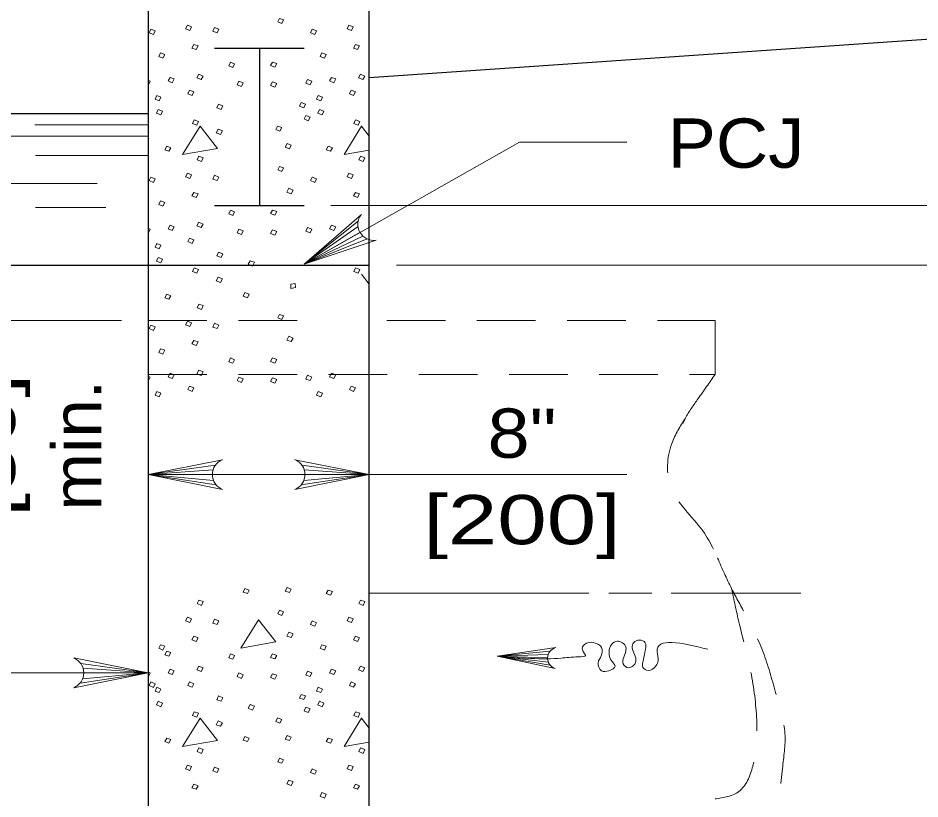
# Model space of a CAD drawing. Extents: x 1083.1 to 1123, y 697.4 to 741.4.
# Drawn here: x 1094.048 to 1096.906, y 701.287 to 703.761 of the extents above; entities that cross this region are included whole.
import ezdxf
from ezdxf.enums import TextEntityAlignment as Align

# ---------------------------------------------------------------- set-up
doc = ezdxf.new("R2010")
doc.units = 0
doc.header["$LTSCALE"] = 0.062
doc.linetypes.add('MEDIUM_DASHED', pattern=[4.5, 3, -1.5])
doc.layers.add('1', color=7, linetype='Continuous', lineweight=13)

msp = doc.modelspace()

# ---------------------------------------------------------------- linework, layer by layer
at = {"layer": '1', "lineweight": 25}
for p, q in [((1095.16083, 699.49442), (1095.16083, 704.3885)), ((1094.45983, 704.08583), (1094.45983, 702.96883)), ((1095.16083, 703.57292), (1099.30092, 703.85675)), ((1094.67075, 703.66558), (1094.95483, 703.66558)), ((1094.81283, 703.66558), (1094.81283, 703.167)), ((1092.13858, 703.45842), (1094.45983, 703.45842)), ((1094.67075, 703.167), (1094.95483, 703.167)), ((1094.45983, 702.97792), (1094.45983, 700.85858))]:
    msp.add_line(p, q, dxfattribs=at)
at = {"layer": '1'}
for p, q in [((1094.10067, 703.42283), (1094.45983, 703.42283)), ((1095.16083, 703.38692), (1095.1365, 703.41817)), ((1093.84958, 703.38742), (1094.45983, 703.38742)), ((1094.10292, 703.32575), (1094.45983, 703.32575)), ((1093.95833, 703.23683), (1094.29858, 703.23683)), ((1094.10292, 703.16125), (1094.32633, 703.16125)), ((1095.03908, 703.167), (1100.20558, 703.167)), ((1095.12558, 703.11725), (1094.95433, 702.98183)), ((1095.12533, 703.10117), (1094.95433, 702.98183)), ((1095.1315, 703.08267), (1094.95433, 702.98183)), ((1095.14092, 703.07067), (1094.95433, 702.98183)), ((1095.1545, 703.06142), (1094.95433, 702.98183)), ((1095.07658, 702.97792), (1094.07242, 702.97792)), ((1095.247, 702.97792), (1100.93725, 702.97792)), ((1095.33125, 702.97792), (1096.6295, 702.97792)), ((1095.16083, 702.91817), (1095.1365, 702.9495)), ((1094.37558, 702.80275), (1093.74558, 702.80275)), ((1094.67317, 702.34492), (1094.45983, 702.31508)), ((1094.9475, 702.34492), (1095.16083, 702.31508)), ((1094.66592, 702.33017), (1094.45983, 702.31508)), ((1094.45983, 702.31508), (1095.97717, 702.31508)), ((1094.66367, 702.31508), (1094.45983, 702.31508)), ((1094.6675, 702.29592), (1094.45983, 702.31508)), ((1094.67567, 702.28208), (1094.45983, 702.31508)), ((1094.945, 702.28208), (1095.16083, 702.31508)), ((1094.95317, 702.29592), (1095.16083, 702.31508)), ((1094.95475, 702.33017), (1095.16083, 702.31508)), ((1094.95692, 702.31508), (1095.16083, 702.31508)), ((1095.85708, 701.93967), (1095.16083, 701.93967)), ((1096.05675, 701.93967), (1095.92, 701.93967)), ((1096.529, 701.93967), (1096.11758, 701.93967)), ((1095.73417, 701.75567), (1095.56583, 701.73925)), ((1095.72808, 701.74533), (1095.56583, 701.73925)), ((1095.726, 701.73475), (1095.56583, 701.73925)), ((1095.7285, 701.72108), (1095.56583, 701.73925)), ((1095.73458, 701.71108), (1095.56583, 701.73925)), ((1094.24658, 701.71675), (1094.45983, 701.68692)), ((1094.24408, 701.65392), (1094.45983, 701.68692)), ((1094.25225, 701.66775), (1094.45983, 701.68692)), ((1094.25383, 701.702), (1094.45983, 701.68692)), ((1094.256, 701.68692), (1094.45983, 701.68692)), ((1095.16083, 701.51208), (1095.1365, 701.54333))]:
    msp.add_line(p, q, dxfattribs=at)
at = {"layer": '1', "linetype": 'MEDIUM_DASHED'}
for p, q in [((1094.45983, 702.80275), (1094.95575, 702.80275)), ((1095.21608, 702.80275), (1096.25675, 702.80275)), ((1096.25675, 702.80275), (1096.25675, 702.63158)), ((1094.45983, 702.63158), (1096.25675, 702.63158))]:
    msp.add_line(p, q, dxfattribs=at)
at = {"layer": '1'}
for points in [[(1094.87608, 703.76), (1094.8895, 703.75517), (1094.88417, 703.74383), (1094.87067, 703.74867)], [(1094.46833, 703.72608), (1094.48183, 703.72042), (1094.47642, 703.70908), (1094.463, 703.71475)], [(1094.58425, 703.73817), (1094.59767, 703.73333), (1094.59225, 703.72125), (1094.57883, 703.72683)], [(1094.67042, 703.73175), (1094.68392, 703.72608), (1094.6785, 703.71475), (1094.665, 703.71958)], [(1094.98025, 703.72608), (1094.99367, 703.72042), (1094.98833, 703.70908), (1094.97483, 703.71475)], [(1095.09608, 703.73817), (1095.10958, 703.73333), (1095.10417, 703.72125), (1095.09067, 703.72683)], [(1094.60492, 703.67758), (1094.61833, 703.67275), (1094.61208, 703.66142), (1094.59858, 703.66625)], [(1095.11675, 703.67758), (1095.13017, 703.67275), (1095.12392, 703.66142), (1095.11042, 703.66625)], [(1094.49892, 703.65092), (1094.51242, 703.64608), (1094.507, 703.63392), (1094.4935, 703.63958)], [(1095.01075, 703.65092), (1095.02425, 703.64608), (1095.01883, 703.63392), (1095.00542, 703.63958)], [(1094.72067, 703.62183), (1094.73417, 703.61617), (1094.72883, 703.60483), (1094.71533, 703.60967)], [(1094.8545, 703.62183), (1094.868, 703.617), (1094.86167, 703.60567), (1094.84825, 703.6105)], [(1094.52942, 703.57333), (1094.54292, 703.5685), (1094.53658, 703.55633), (1094.52317, 703.562)], [(1094.621, 703.583), (1094.6345, 703.57742), (1094.62825, 703.56608), (1094.61475, 703.57175)], [(1095.04133, 703.57333), (1095.05475, 703.5685), (1095.0485, 703.55633), (1095.035, 703.562)], [(1095.13292, 703.583), (1095.14633, 703.57742), (1095.14008, 703.56608), (1095.12658, 703.57175)], [(1094.74767, 703.56125), (1094.76108, 703.55558), (1094.75575, 703.54425), (1094.74225, 703.54992)], [(1094.8545, 703.55883), (1094.868, 703.55392), (1094.86167, 703.54183), (1094.84825, 703.5475)], [(1094.965, 703.56683), (1094.97842, 703.56125), (1094.97308, 703.54992), (1094.95958, 703.55475)], [(1094.48725, 703.516), (1094.50067, 703.51033), (1094.49533, 703.499), (1094.48183, 703.50383)], [(1094.59142, 703.53292), (1094.60492, 703.52725), (1094.5995, 703.516), (1094.586, 703.52158)], [(1094.99908, 703.516), (1095.01258, 703.51033), (1095.00717, 703.499), (1094.99367, 703.50383)], [(1095.10325, 703.53292), (1095.11675, 703.52725), (1095.11133, 703.516), (1095.09783, 703.52158)], [(1094.683, 703.4885), (1094.6965, 703.48283), (1094.69108, 703.4715), (1094.67758, 703.47633)], [(1094.94517, 703.49333), (1094.95867, 703.4885), (1094.95333, 703.47717), (1094.93983, 703.482)], [(1094.49175, 703.4715), (1094.50517, 703.46583), (1094.49983, 703.45458), (1094.48633, 703.46017)], [(1095.00358, 703.4715), (1095.01708, 703.46583), (1095.01167, 703.45458), (1094.99817, 703.46017)], [(1094.60575, 703.43842), (1094.61925, 703.4335), (1094.61383, 703.42142), (1094.60042, 703.42708)], [(1094.95958, 703.45292), (1094.97308, 703.44725), (1094.96767, 703.43592), (1094.95417, 703.44158)], [(1095.11767, 703.43842), (1095.13108, 703.4335), (1095.12575, 703.42142), (1095.11225, 703.42708)], [(1094.62467, 703.41817), (1094.56892, 703.3285), (1094.67942, 703.34783)], [(1094.68208, 703.40925), (1094.69558, 703.40367), (1094.68925, 703.39233), (1094.67583, 703.39717)], [(1094.86975, 703.419), (1094.88325, 703.41417), (1094.87783, 703.40283), (1094.86442, 703.40767)], [(1094.51867, 703.35517), (1094.53217, 703.35033), (1094.52583, 703.339), (1094.51242, 703.34383)], [(1094.90033, 703.36325), (1094.91375, 703.35842), (1094.9075, 703.34708), (1094.894, 703.35192)], [(1095.0305, 703.35517), (1095.044, 703.35033), (1095.03767, 703.339), (1095.02425, 703.34383)], [(1094.621, 703.32367), (1094.6345, 703.31875), (1094.62908, 703.30667), (1094.61567, 703.31233)], [(1095.13292, 703.32367), (1095.14633, 703.31875), (1095.141, 703.30667), (1095.1275, 703.31233)], [(1094.87608, 703.29133), (1094.8895, 703.28642), (1094.88417, 703.27517), (1094.87067, 703.28)], [(1094.46833, 703.25733), (1094.48183, 703.25167), (1094.47642, 703.24042), (1094.463, 703.24608)], [(1094.58425, 703.2695), (1094.59767, 703.26467), (1094.59225, 703.2525), (1094.57883, 703.25817)], [(1094.67042, 703.263), (1094.68392, 703.25733), (1094.6785, 703.24608), (1094.665, 703.25092)], [(1094.98025, 703.25733), (1094.99367, 703.25167), (1094.98833, 703.24042), (1094.97483, 703.24608)], [(1095.09608, 703.2695), (1095.10958, 703.26467), (1095.10417, 703.2525), (1095.09067, 703.25817)], [(1094.60492, 703.20883), (1094.61833, 703.204), (1094.61208, 703.19275), (1094.59858, 703.19758)], [(1094.90567, 703.22183), (1094.91917, 703.21617), (1094.91292, 703.20483), (1094.89942, 703.20967)], [(1095.11675, 703.20883), (1095.13017, 703.204), (1095.12392, 703.19275), (1095.11042, 703.19758)], [(1094.49892, 703.18225), (1094.51242, 703.17733), (1094.507, 703.16525), (1094.4935, 703.17092)], [(1094.72067, 703.15308), (1094.73417, 703.1475), (1094.72883, 703.13617), (1094.71533, 703.141)], [(1094.8545, 703.15308), (1094.868, 703.14825), (1094.86167, 703.13692), (1094.84825, 703.14183)], [(1094.621, 703.11433), (1094.6345, 703.10867), (1094.62825, 703.09733), (1094.61475, 703.103)], [(1094.52942, 703.10467), (1094.54292, 703.09975), (1094.53658, 703.08767), (1094.52317, 703.09333)], [(1094.74767, 703.0925), (1094.76108, 703.08683), (1094.75575, 703.0755), (1094.74225, 703.08117)], [(1094.8545, 703.09008), (1094.868, 703.08525), (1094.86167, 703.07308), (1094.84825, 703.07875)], [(1094.965, 703.09817), (1094.97842, 703.0925), (1094.97308, 703.08117), (1094.95958, 703.086)], [(1095.04133, 703.10467), (1095.05475, 703.09975), (1095.0485, 703.08767), (1095.035, 703.09333)], [(1094.59142, 703.06425), (1094.60492, 703.05858), (1094.5995, 703.04725), (1094.586, 703.05292)], [(1094.48725, 703.04725), (1094.50067, 703.04158), (1094.49533, 703.03025), (1094.48183, 703.03517)], [(1094.49175, 703.00283), (1094.50517, 702.99717), (1094.49983, 702.98583), (1094.48633, 702.9915)], [(1094.683, 703.01975), (1094.6965, 703.01408), (1094.69108, 703.00283), (1094.67758, 703.00767)], [(1094.60575, 702.96967), (1094.61925, 702.96483), (1094.61383, 702.95267), (1094.60042, 702.95833)], [(1094.78358, 702.99233), (1094.797, 702.98742), (1094.79075, 702.97533), (1094.77725, 702.981)], [(1095.11767, 702.96967), (1095.13108, 702.96483), (1095.12575, 702.95267), (1095.11225, 702.95833)], [(1094.68208, 702.94058), (1094.69558, 702.93492), (1094.68925, 702.92358), (1094.67583, 702.9285)], [(1094.92692, 702.90742), (1094.91258, 702.90492), (1094.91175, 702.91783), (1094.92617, 702.92033)], [(1094.51867, 702.88642), (1094.53217, 702.88158), (1094.52583, 702.87025), (1094.51242, 702.87517)], [(1094.7665, 702.89133), (1094.78, 702.88642), (1094.77458, 702.87517), (1094.76108, 702.88)], [(1094.621, 702.85492), (1094.6345, 702.85008), (1094.62908, 702.83792), (1094.61567, 702.84358)], [(1094.58425, 702.80075), (1094.59767, 702.79592), (1094.59225, 702.78383), (1094.57883, 702.7895)], [(1094.87608, 702.82258), (1094.8895, 702.81775), (1094.88417, 702.80642), (1094.87067, 702.81125)], [(1094.46833, 702.78867), (1094.48183, 702.783), (1094.47642, 702.77167), (1094.463, 702.77733)], [(1094.67042, 702.79433), (1094.68392, 702.78867), (1094.6785, 702.77733), (1094.665, 702.78217)], [(1094.60492, 702.74017), (1094.61833, 702.73533), (1094.61208, 702.724), (1094.59858, 702.72883)], [(1094.90567, 702.75308), (1094.91917, 702.74742), (1094.91292, 702.73617), (1094.89942, 702.741)], [(1094.49892, 702.7135), (1094.51242, 702.70867), (1094.507, 702.6965), (1094.4935, 702.70217)], [(1094.72067, 702.68442), (1094.73417, 702.67875), (1094.72883, 702.66742), (1094.71533, 702.67225)], [(1094.8545, 702.68442), (1094.868, 702.67958), (1094.86167, 702.66825), (1094.84825, 702.67308)], [(1094.52942, 702.63592), (1094.54292, 702.63108), (1094.53658, 702.61892), (1094.52317, 702.62458)], [(1094.621, 702.64558), (1094.6345, 702.64), (1094.62825, 702.62867), (1094.61475, 702.63433)], [(1094.965, 702.62942), (1094.97842, 702.62383), (1094.97308, 702.6125), (1094.95958, 702.61733)], [(1095.04133, 702.63592), (1095.05475, 702.63108), (1095.0485, 702.61892), (1095.035, 702.62458)], [(1094.74767, 702.62383), (1094.76108, 702.61817), (1094.75575, 702.60683), (1094.74225, 702.6125)], [(1094.8545, 702.62133), (1094.868, 702.6165), (1094.86167, 702.60442), (1094.84825, 702.61008)], [(1094.48725, 702.57858), (1094.50067, 702.57292), (1094.49533, 702.56158), (1094.48183, 702.56642)], [(1094.59142, 702.5955), (1094.60492, 702.58983), (1094.5995, 702.57858), (1094.586, 702.58417)], [(1094.99908, 702.57858), (1095.01258, 702.57292), (1095.00717, 702.56158), (1094.99367, 702.56642)], [(1095.10325, 702.5955), (1095.11675, 702.58983), (1095.11133, 702.57858), (1095.09783, 702.58417)], [(1094.7665, 701.95383), (1094.78, 701.949), (1094.77458, 701.93775), (1094.76108, 701.94258)], [(1094.90033, 701.95708), (1094.91375, 701.95225), (1094.9075, 701.94092), (1094.894, 701.94575)], [(1095.0305, 701.949), (1095.044, 701.94417), (1095.03767, 701.93283), (1095.02425, 701.93775)], [(1094.621, 701.9175), (1094.6345, 701.91267), (1094.62908, 701.9005), (1094.61567, 701.90617)], [(1095.13292, 701.9175), (1095.14633, 701.91267), (1095.141, 701.9005), (1095.1275, 701.90617)], [(1094.87608, 701.88517), (1094.8895, 701.88033), (1094.88417, 701.869), (1094.87067, 701.87383)], [(1094.58425, 701.86333), (1094.59767, 701.8585), (1094.59225, 701.84642), (1094.57883, 701.85208)], [(1094.67042, 701.85692), (1094.68392, 701.85125), (1094.6785, 701.83992), (1094.665, 701.84475)], [(1094.80958, 701.85525), (1094.75392, 701.76558), (1094.86442, 701.785)], [(1095.09608, 701.86333), (1095.10958, 701.8585), (1095.10417, 701.84642), (1095.09067, 701.85208)], [(1094.98025, 701.85125), (1094.99367, 701.84558), (1094.98833, 701.83425), (1094.97483, 701.83992)], [(1094.60492, 701.80275), (1094.61833, 701.79792), (1094.61208, 701.78658), (1094.59858, 701.79142)], [(1094.90567, 701.81567), (1094.91917, 701.81), (1094.91292, 701.79875), (1094.89942, 701.80358)], [(1095.11675, 701.80275), (1095.13017, 701.79792), (1095.12392, 701.78658), (1095.11042, 701.79142)], [(1094.49892, 701.77608), (1094.51242, 701.77125), (1094.507, 701.75908), (1094.4935, 701.76475)], [(1095.01075, 701.77608), (1095.02425, 701.77125), (1095.01883, 701.75908), (1095.00542, 701.76475)], [(1094.51867, 701.75575), (1094.53217, 701.75092), (1094.52583, 701.73958), (1094.51242, 701.74442)], [(1094.72067, 701.747), (1094.73417, 701.74133), (1094.72883, 701.73), (1094.71533, 701.73483)], [(1094.8545, 701.747), (1094.868, 701.74217), (1094.86167, 701.73083), (1094.84825, 701.73567)], [(1094.52942, 701.6985), (1094.54292, 701.69367), (1094.53658, 701.6815), (1094.52317, 701.68717)], [(1094.621, 701.70817), (1094.6345, 701.7025), (1094.62825, 701.69125), (1094.61475, 701.69692)], [(1094.74767, 701.68642), (1094.76108, 701.68075), (1094.75575, 701.66942), (1094.74225, 701.67508)], [(1094.8545, 701.684), (1094.868, 701.67908), (1094.86167, 701.667), (1094.84825, 701.67267)], [(1094.965, 701.692), (1094.97842, 701.68642), (1094.97308, 701.67508), (1094.95958, 701.67992)], [(1095.04133, 701.6985), (1095.05475, 701.69367), (1095.0485, 701.6815), (1095.035, 701.68717)], [(1095.13292, 701.70817), (1095.14633, 701.7025), (1095.14008, 701.69125), (1095.12658, 701.69692)], [(1094.46833, 701.65792), (1094.48183, 701.65233), (1094.47642, 701.641), (1094.463, 701.64667)], [(1094.59142, 701.65808), (1094.60492, 701.65242), (1094.5995, 701.64117), (1094.586, 701.64675)], [(1095.10325, 701.65808), (1095.11675, 701.65242), (1095.11133, 701.64117), (1095.09783, 701.64675)], [(1094.48725, 701.64117), (1094.50067, 701.6355), (1094.49533, 701.62417), (1094.48183, 701.629)], [(1094.99908, 701.64117), (1095.01258, 701.6355), (1095.00717, 701.62417), (1094.99367, 701.629)], [(1094.49175, 701.59667), (1094.50517, 701.591), (1094.49983, 701.57975), (1094.48633, 701.58533)], [(1094.683, 701.61367), (1094.6965, 701.608), (1094.69108, 701.59667), (1094.67758, 701.6015)], [(1094.94517, 701.6185), (1094.95867, 701.61367), (1094.95333, 701.60233), (1094.93983, 701.60717)], [(1095.00358, 701.59667), (1095.01708, 701.591), (1095.01167, 701.57975), (1094.99817, 701.58533)], [(1094.78358, 701.58617), (1094.797, 701.58133), (1094.79075, 701.56917), (1094.77725, 701.57483)], [(1094.95958, 701.57808), (1094.97308, 701.57242), (1094.96767, 701.56117), (1094.95417, 701.56675)], [(1094.62467, 701.54333), (1094.56892, 701.45367), (1094.67942, 701.473)], [(1094.60575, 701.56358), (1094.61925, 701.55867), (1094.61383, 701.54658), (1094.60042, 701.55225)], [(1094.86975, 701.54417), (1094.88325, 701.53933), (1094.87783, 701.528), (1094.86442, 701.53283)], [(1095.11767, 701.56358), (1095.13108, 701.55867), (1095.12575, 701.54658), (1095.11225, 701.55225)], [(1094.68208, 701.53442), (1094.69558, 701.52883), (1094.68925, 701.5175), (1094.67583, 701.52233)], [(1094.7665, 701.48517), (1094.78, 701.48033), (1094.77458, 701.469), (1094.76108, 701.47383)], [(1094.90033, 701.48842), (1094.91375, 701.48358), (1094.9075, 701.47225), (1094.894, 701.47708)], [(1094.51867, 701.48033), (1094.53217, 701.4755), (1094.52583, 701.46417), (1094.51242, 701.469)], [(1095.0305, 701.48033), (1095.044, 701.4755), (1095.03767, 701.46417), (1095.02425, 701.469)], [(1094.621, 701.44883), (1094.6345, 701.44392), (1094.62908, 701.43183), (1094.61567, 701.4375)], [(1095.13292, 701.44883), (1095.14633, 701.44392), (1095.141, 701.43183), (1095.1275, 701.4375)], [(1094.87608, 701.4165), (1094.8895, 701.41167), (1094.88417, 701.40033), (1094.87067, 701.40517)], [(1094.58425, 701.39467), (1094.59767, 701.38983), (1094.59225, 701.37767), (1094.57883, 701.38333)], [(1094.67042, 701.38817), (1094.68392, 701.3825), (1094.6785, 701.37125), (1094.665, 701.37608)], [(1094.98025, 701.3825), (1094.99367, 701.37683), (1094.98833, 701.36558), (1094.97483, 701.37125)], [(1095.09608, 701.39467), (1095.10958, 701.38983), (1095.10417, 701.37767), (1095.09067, 701.38333)], [(1094.90567, 701.347), (1094.91917, 701.34133), (1094.91292, 701.33), (1094.89942, 701.33483)], [(1094.60492, 701.33408), (1094.61833, 701.32917), (1094.61208, 701.31792), (1094.59858, 701.32275)], [(1095.11675, 701.33408), (1095.13017, 701.32917), (1095.12392, 701.31792), (1095.11042, 701.32275)], [(1095.01075, 701.30742), (1095.02425, 701.3025), (1095.01883, 701.29042), (1095.00542, 701.29608)]]:
    msp.add_lwpolyline(points, close=True, dxfattribs=at)
for points in [[(1094.45983, 703.564), (1094.46658, 703.56125), (1094.46117, 703.54992), (1094.45983, 703.55042)], [(1094.45983, 703.44783), (1094.46117, 703.44725), (1094.45983, 703.44442)], [(1095.1365, 703.41817), (1095.08083, 703.3285), (1095.16083, 703.3425)], [(1094.95433, 702.98183), (1095.63692, 703.36842), (1095.97717, 703.36842)], [(1095.13583, 703.13933), (1094.95433, 702.98183), (1095.18242, 703.05742)], [(1094.45983, 703.09533), (1094.46658, 703.0925), (1094.46117, 703.08117), (1094.45983, 703.08167)], [(1094.45983, 702.97908), (1094.46117, 702.97858), (1094.45983, 702.97575)], [(1094.45983, 702.62667), (1094.46658, 702.62383), (1094.46117, 702.6125), (1094.45983, 702.613)], [(1094.45983, 702.51042), (1094.46117, 702.50983), (1094.45983, 702.507)], [(1094.69542, 702.26792), (1094.45983, 702.31508), (1094.69542, 702.36217)], [(1094.92525, 702.26792), (1095.16083, 702.31508), (1094.92525, 702.36217)], [(1094.45983, 702.218), (1094.46117, 702.21742), (1094.45983, 702.21458)], [(1095.74983, 701.70067), (1095.56583, 701.73925), (1095.75208, 701.76733)], [(1094.22425, 701.63975), (1094.45983, 701.68692), (1094.22425, 701.734)], [(1092.13858, 701.68692), (1093.89508, 701.68692), (1094.45983, 701.68692)], [(1094.45983, 701.68925), (1094.46658, 701.68642), (1094.46117, 701.67508), (1094.45983, 701.67558)], [(1094.45983, 701.573), (1094.46117, 701.57242), (1094.45983, 701.56958)], [(1095.1365, 701.54333), (1095.08083, 701.45367), (1095.16083, 701.46767)]]:
    msp.add_lwpolyline(points, dxfattribs=at)
at = {"layer": '1', "lineweight": 25}
msp.add_lwpolyline([(1091.42492, 702.97792), (1092.13858, 702.97792), (1095.16083, 702.97792)], dxfattribs=at)
at = {"layer": '1'}
for centre, start, end in [((1095.17566, 703.10773), 141.73751, 277.56363), ((1094.71446, 702.31511), 112.08782, 247.91395), ((1094.90621, 702.31511), 292.08605, 67.91218), ((1094.20524, 701.68694), 292.08605, 67.91218)]:
    msp.add_arc(centre, 0.05085, start, end, dxfattribs=at)
msp.add_ellipse((1095.76597, 701.73359), major_axis=(-0.03997, 0), ratio=0.899905, start_param=5.0665441, end_param=7.4371572, dxfattribs=at)
at = {"layer": '1', "linetype": 'MEDIUM_DASHED'}
for points in [[(1096.25675, 702.63158), (1096.20333, 702.5555), (1096.16242, 702.49292), (1096.15175, 702.47108)], [(1096.16292, 702.49375), (1096.11958, 702.41342), (1096.11642, 702.27633), (1096.21808, 702.13625), (1096.28117, 702.01533)], [(1096.26467, 702.0505), (1096.3095, 701.95358), (1096.35508, 701.86883), (1096.41217, 701.7445), (1096.45117, 701.617), (1096.47833, 701.49367), (1096.47042, 701.384), (1096.44308, 701.23358), (1096.36575, 701.124), (1096.25675, 701.07533)], [(1096.25675, 701.28742), (1096.33233, 701.31108), (1096.3765, 701.39142), (1096.38892, 701.53767), (1096.37033, 701.69017), (1096.33267, 701.847), (1096.3095, 701.95358)]]:
    msp.add_spline(points, degree=3, dxfattribs=at)
at = {"layer": '1'}
msp.add_spline([(1096.23367, 701.76192), (1096.0735, 701.75383), (1096.07658, 701.72458), (1096.07017, 701.71), (1096.0445, 701.69442), (1096.0285, 701.70383), (1096.02967, 701.72783), (1096.03617, 701.76125), (1096.03525, 701.78217), (1096.01708, 701.79058), (1095.99892, 701.78225), (1095.9945, 701.76658), (1096.00192, 701.74458), (1096.00608, 701.72475), (1095.99425, 701.707), (1095.97717, 701.70392), (1095.96442, 701.72067), (1095.96992, 701.74258), (1095.97325, 701.77183), (1095.95942, 701.78433), (1095.94233, 701.7865), (1095.92517, 701.77192), (1095.92083, 701.75), (1095.93142, 701.72167), (1095.93983, 701.70808), (1095.9205, 701.69358), (1095.89708, 701.69358), (1095.8865, 701.71875), (1095.89617, 701.74058), (1095.89733, 701.76675), (1095.874, 701.78242), (1095.843, 701.77717), (1095.8365, 701.7595), (1095.846, 701.74175), (1095.82467, 701.73758), (1095.76908, 701.7335), (1095.56583, 701.73925)], degree=3, dxfattribs=at)

# ---------------------------------------------------------------- texts
at = {"layer": '1', "width": 1.1}
msp.add_text('PCJ', height=0.156, dxfattribs=at).set_placement((1096.10642, 703.287))
at = {"layer": '1'}
for s, width, p in [('[50]', 1.3, (1094.03808, 702.40771)), ('min.', 1.05, (1094.31208, 702.40775))]:
    msp.add_text(s, height=0.156, rotation=90, dxfattribs=dict(at, width=width)).set_placement(p, align=Align.CENTER)
for s, width, p in [('8"', 1.15, (1095.645, 702.36825)), ('[200]', 1.35, (1095.645, 702.09425))]:
    msp.add_text(s, height=0.156, dxfattribs=dict(at, width=width)).set_placement(p, align=Align.CENTER)

doc.saveas('drawing.dxf')
